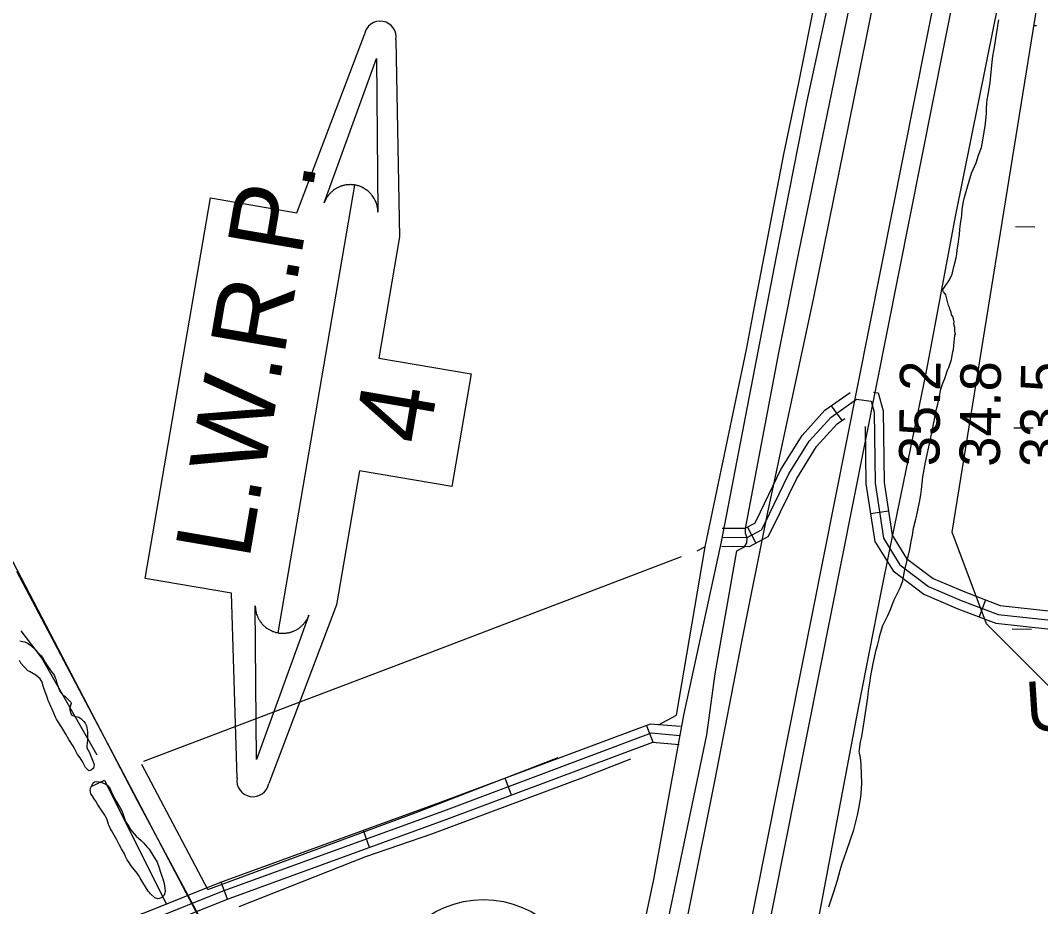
# Model space of a CAD drawing. Extents: x 3271442 to 3309282, y 752266 to 777610.
# Drawn here: x 3282681 to 3284369, y 758921 to 760386 of the extents above; entities that cross this region are included whole.
import ezdxf

# ---------------------------------------------------------------- set-up
doc = ezdxf.new("R2010")
doc.units = 0
for name, color, linetype in [('V-LEVE-TOET', 7, 'Continuous'), ('V-RAIL-TRAK', 7, 'Continuous'), ('V-RIVR-RANG', 7, 'Continuous'), ('V-RIVR-RANG-IDEN', 7, 'Continuous'), ('V-ROAD-CNTR', 7, 'Continuous'), ('V-ROAD-IDEN', 7, 'Continuous'), ('V-SITE-VEGE', 7, 'Continuous'), ('V-SURV-LINE', 7, 'Continuous'), ('V-TOPO-SHOR', 7, 'Continuous'), ('V-TOPO-WATR-IDEN', 7, 'Continuous'), ('V-WETL-SWMP', 7, 'Continuous')]:
    doc.layers.add(name, color=color, linetype=linetype)

msp = doc.modelspace()

# ---------------------------------------------------------------- linework, layer by layer
at = {"layer": 'V-LEVE-TOET'}
for points in [[(3284382.2, 761838.2), (3284344.5, 761627.4), (3284315.7, 761468.6), (3284259.5, 761217.6), (3284245.5, 761153.1), (3284211.7, 761000.5), (3284141.1, 760659.9), (3284068.8, 760300.7), (3283992.3, 759925.7), (3283917, 759573.3), (3283873.8, 759359.2), (3283829.2, 759128.8), (3283789.2, 758928.4), (3283748.2, 758723.2), (3283716.1, 758548.7), (3283700.8, 758474.2), (3283696.3, 758451.7), (3283694.3, 758422.9), (3283700.6, 758324), (3283715.2, 758155.8), (3283736.7, 757909.8), (3283747.6, 757720.6), (3283753.7, 757644)], [(3283974.8, 757644.1), (3283959.8, 757827.3), (3283934.6, 758131.3), (3283909.7, 758337.4), (3283903.2, 758406.3), (3283904.4, 758428.5), (3283911.5, 758459.3), (3283917.8, 758511.7), (3283957.3, 758687.2), (3284002, 758902.8), (3284068.3, 759252.9), (3284104.5, 759438), (3284120.1, 759514.3), (3284179.5, 759803.5), (3284227.8, 760062.5), (3284292, 760379.3), (3284364.4, 760732.6), (3284401.6, 760905.6)]]:
    msp.add_lwpolyline(points, dxfattribs=at)
at = {"layer": 'V-RAIL-TRAK'}
msp.add_lwpolyline([(3283548.1, 757644), (3283531.8, 757704.4), (3283489.6, 757836.6), (3283430.4, 757998.5), (3283369.2, 758143.7), (3283305.6, 758276.6), (3283244.5, 758396.3), (3283128.2, 758616.7), (3282975.9, 758905.4), (3282961, 758933.9), (3282846.4, 759151.6), (3282675.5, 759475.3)], dxfattribs=at)
at = {"layer": 'V-ROAD-CNTR'}
for p, q in [((3284022.6, 759749.3), (3284039.8, 759724.8)), ((3284117.2, 759575.2), (3284087.6, 759570.6)), ((3283883.9, 759548.9), (3283897.8, 759522.3)), ((3284277.6, 759428.4), (3284266.9, 759400.3)), ((3283727.7, 759193), (3283717.1, 759221.1)), ((3283493.5, 759105.4), (3283483, 759133.5)), ((3283258.8, 759018.9), (3283248.6, 759047.1)), ((3283023.9, 758933.5), (3283013.6, 758961.7))]:
    msp.add_line(p, q, dxfattribs=at)
for points in [[(3284392.4, 762318.9), (3284315.3, 761934.3), (3284255.9, 761629.7), (3284216.4, 761423.6), (3284162.8, 761165.1), (3284106.1, 760889.3), (3284031, 760479.6), (3283981.6, 760250.5), (3283931.6, 759996.1), (3283883.2, 759747.5), (3283840.4, 759524.6), (3283778.2, 759237.6), (3283728.5, 758966.2), (3283675.1, 758714.9), (3283635.4, 758490.5)], [(3281661.2, 761410.7), (3281877.3, 760997.6), (3282056.3, 760659.9), (3282250.8, 760283.5), (3282415.3, 759970.5), (3282620.5, 759583.3), (3282874.5, 759096.9), (3283005, 758852.9), (3283121.9, 758631.6), (3283211.6, 758466.4), (3283271.5, 758351.6), (3283316, 758260.4), (3283364.8, 758166.5), (3283397.9, 758090), (3283446.7, 757970.9), (3283502, 757821.2), (3283536.5, 757705.1), (3283551.4, 757646.8)], [(3283842, 759547.2), (3283879.9, 759546.8), (3283896.1, 759555.3), (3283898.7, 759560.3), (3283939.3, 759643.9), (3283974.2, 759700), (3284012.1, 759742), (3284053.6, 759771.1)], [(3284092.6, 759771.6), (3284100, 759770.6), (3284108.4, 759741.1), (3284109.9, 759622.7), (3284123.3, 759535.6), (3284147.2, 759496.8), (3284191, 759463.9), (3284243.2, 759441.5), (3284301.8, 759419.1), (3284386.7, 759409.8), (3284510.2, 759410.6), (3284567.2, 759379.4), (3284575.9, 759344.6)], [(3283841.8, 759532.2), (3283883.5, 759531.7), (3283907.2, 759544.2), (3283912.1, 759553.6), (3283952.5, 759636.6), (3283986.2, 759691), (3284022.1, 759730.7), (3284064.1, 759760.2), (3284088.3, 759757), (3284093.5, 759738.9), (3284094.9, 759621.4), (3284109, 759530.3), (3284135.9, 759486.6), (3284183.4, 759450.8), (3284237.6, 759427.6), (3284298.3, 759404.4), (3284385.9, 759394.8), (3284506.4, 759395.5), (3284554.2, 759369.4), (3284561.3, 759340.9)], [(3283841.7, 759517.2), (3283887.1, 759516.7), (3283918.4, 759533.1), (3283925.5, 759546.9), (3283965.6, 759629.4), (3283998.2, 759681.9), (3284032.1, 759719.3), (3284045.1, 759728.5)], [(3284078.7, 759715.3), (3284079.9, 759620.2), (3284094.6, 759525.1), (3284124.6, 759476.3), (3284175.8, 759437.8), (3284232, 759413.7), (3284294.7, 759389.7), (3284385.1, 759379.8), (3284502.6, 759380.5), (3284541.3, 759359.4), (3284546.7, 759337.3)], [(3283773.4, 759218.9), (3283722.7, 759223.2), (3283375.8, 759093.3), (3283010.9, 758960.7), (3282890.1, 758912.1), (3282473.8, 758758.6), (3282222.7, 758663.5), (3282085.2, 758594.3), (3281867.3, 758517), (3281707, 758457), (3281582.4, 758417.7)], [(3283772.1, 759203.9), (3283724.8, 759208), (3283380.9, 759079.2), (3283016.2, 758946.7), (3282895.5, 758898.1), (3282479.1, 758744.6), (3282228.7, 758649.7), (3282091.1, 758580.4), (3281872.4, 758502.9), (3281711.8, 758442.8), (3281586.5, 758403.2)], [(3283770.8, 759189), (3283726.9, 759192.7), (3283386.1, 759065.1), (3283021.6, 758932.7), (3282900.9, 758884.1), (3282484.3, 758730.5), (3282234.8, 758636), (3282097, 758566.6), (3281877.6, 758488.8), (3281716.7, 758428.7), (3281590.6, 758388.8)]]:
    msp.add_lwpolyline(points, dxfattribs=at)
at = {"layer": 'V-ROAD-IDEN'}
msp.add_circle((3283447.3, 758768), 165, dxfattribs=at)
at = {"layer": 'V-SITE-VEGE'}
for p, q in [((3284296.2, 760366.8), (3284297.5, 760373.1)), ((3284297.5, 760373.1), (3284298.3, 760381.9)), ((3284298.3, 760381.9), (3284299.6, 760387.7)), ((3284293.6, 760348.8), (3284294.5, 760356.3)), ((3284294.5, 760356.3), (3284296.2, 760366.8)), ((3284291.1, 760336.2), (3284293.6, 760348.8)), ((3284288.6, 760317.3), (3284289.8, 760327.4)), ((3284289.8, 760327.4), (3284291.1, 760336.2)), ((3284285.1, 760283.4), (3284287.3, 760306.8)), ((3284287.3, 760306.8), (3284288.6, 760317.3)), ((3284281.8, 760264.1), (3284285.1, 760283.4)), ((3284279.6, 760249.4), (3284280.1, 760255.3)), ((3284280.1, 760255.3), (3284281.8, 760264.1)), ((3284279.2, 760240.2), (3284279.6, 760249.4)), ((3284279.2, 760233.1), (3284279.2, 760240.2)), ((3284277.1, 760211.7), (3284277.9, 760221.3)), ((3284277.9, 760221.3), (3284279.2, 760233.1)), ((3284274.1, 760195.8), (3284277.1, 760211.7)), ((3284270.7, 760176.5), (3284273.2, 760188.7)), ((3284273.2, 760188.7), (3284274.1, 760195.8)), ((3284266.1, 760163.9), (3284270.7, 760176.5)), ((3284261.9, 760150.9), (3284266.1, 760163.9)), ((3284254.7, 760134.2), (3284261.9, 760150.9)), ((3284248, 760111.6), (3284254.7, 760134.2)), ((3284242.9, 760094), (3284245.4, 760103.6)), ((3284245.4, 760103.6), (3284248, 760111.6)), ((3284239.1, 760074.3), (3284241.2, 760087.3)), ((3284241.2, 760087.3), (3284242.9, 760094)), ((3284238.2, 760064.2), (3284239.1, 760074.3)), ((3284236.5, 760050.4), (3284238.2, 760064.2)), ((3284234.4, 760031.9), (3284235.3, 760041.6)), ((3284235.3, 760041.6), (3284236.5, 760050.4)), ((3284230.6, 760006.4), (3284233.1, 760020.6)), ((3284233.1, 760020.6), (3284234, 760029.4)), ((3284234, 760029.4), (3284234.4, 760031.9)), ((3284230.1, 760000.5), (3284230.6, 760006.4)), ((3284225.9, 759981.2), (3284228.9, 759994.2)), ((3284228.9, 759994.2), (3284230.1, 760000.5)), ((3284222.5, 759967), (3284225.9, 759981.2)), ((3284209.9, 759945.6), (3284217.9, 759957.8)), ((3284217.9, 759957.8), (3284222.5, 759967)), ((3284207, 759939.8), (3284207.8, 759941.9)), ((3284208.2, 759937.7), (3284207, 759939.8)), ((3284207.8, 759941.9), (3284209.9, 759945.6)), ((3284210.7, 759934.7), (3284208.2, 759937.7)), ((3284212, 759932.6), (3284210.7, 759934.7)), ((3284214.1, 759924.2), (3284212, 759932.6)), ((3284216.6, 759915.4), (3284214.1, 759924.2)), ((3284217.8, 759912.1), (3284216.6, 759915.4)), ((3284218.7, 759909.1), (3284217.8, 759912.1)), ((3284219.5, 759907), (3284218.7, 759909.1)), ((3284220.8, 759903.3), (3284219.5, 759907)), ((3284221.6, 759899.9), (3284220.8, 759903.3)), ((3284223.3, 759897), (3284221.6, 759899.9)), ((3284224.9, 759893.2), (3284223.3, 759897)), ((3284225.8, 759888.2), (3284224.9, 759893.2)), ((3284225.3, 759885.7), (3284225.8, 759888.2)), ((3284225.7, 759881.9), (3284225.3, 759885.7)), ((3284224.8, 759842.5), (3284227, 759865.9)), ((3284226.6, 759878.5), (3284225.7, 759881.9)), ((3284227, 759872.7), (3284226.6, 759878.5)), ((3284227.8, 759868), (3284227, 759872.7)), ((3284227, 759865.9), (3284227.8, 759868)), ((3284221.3, 759825.6), (3284223.6, 759838.6)), ((3284223.6, 759838.6), (3284224.8, 759842.5)), ((3284216.9, 759812.6), (3284221.3, 759825.6)), ((3284210.4, 759794.7), (3284215, 759808.2)), ((3284215, 759808.2), (3284216.9, 759812.6)), ((3284203.5, 759776.7), (3284207.2, 759786.7)), ((3284207.2, 759786.7), (3284210.4, 759794.7)), ((3284198.6, 759751.8), (3284203.5, 759776.7)), ((3284194.8, 759737.7), (3284198.6, 759751.8)), ((3284193.1, 759726.7), (3284194.8, 759737.7)), ((3284189.3, 759708.4), (3284193.1, 759726.7)), ((3284186.4, 759694.2), (3284189.3, 759708.4)), ((3284178.3, 759656.4), (3284186.4, 759694.2)), ((3284173.7, 759632.1), (3284177, 759650.2)), ((3284177, 759650.2), (3284178.3, 759656.4)), ((3284172.9, 759621.4), (3284173.7, 759632.1)), ((3284171.8, 759610.8), (3284172.9, 759621.4)), ((3284168.5, 759589.8), (3284170.5, 759601.9)), ((3284170.5, 759601.9), (3284171.8, 759610.8)), ((3284163.4, 759566.1), (3284168.5, 759589.8)), ((3284162.1, 759562), (3284163.4, 759566.1)), ((3284156.6, 759535.7), (3284158.6, 759547.2)), ((3284158.6, 759547.2), (3284162.1, 759562)), ((3284154.6, 759525), (3284156.6, 759535.7)), ((3284151.7, 759509.1), (3284154.6, 759525)), ((3284144.3, 759478.6), (3284151.7, 759509.1)), ((3284142, 759466.8), (3284144.3, 759478.6)), ((3284140.7, 759459.7), (3284142, 759466.8)), ((3284126.8, 759428.8), (3284136.7, 759448.2)), ((3284136.7, 759448.2), (3284140.7, 759459.7)), ((3284122.8, 759418.5), (3284126.8, 759428.8)), ((3284116, 759402.6), (3284120.3, 759412.6)), ((3284120.3, 759412.6), (3284122.8, 759418.5)), ((3284108, 759386.1), (3284112.6, 759396.1)), ((3284112.6, 759396.1), (3284116, 759402.6)), ((3284102.3, 759367.8), (3284108, 759386.1)), ((3284099.1, 759353), (3284101.7, 759364)), ((3284101.7, 759364), (3284102.3, 759367.8)), ((3284091.8, 759323.2), (3284096.9, 759345.9)), ((3284096.9, 759345.9), (3284099.1, 759353)), ((3284087.5, 759300.1), (3284091.8, 759323.2)), ((3284084.2, 759278.2), (3284086.8, 759294.8)), ((3284086.8, 759294.8), (3284087.5, 759300.1)), ((3284082.8, 759267), (3284084.2, 759278.2)), ((3284080.1, 759248.9), (3284082.8, 759267)), ((3284077.4, 759230.6), (3284080.1, 759248.9)), ((3284073, 759202.7), (3284077.4, 759230.6)), ((3284070.2, 759189.7), (3284070.8, 759193.9)), ((3284070.8, 759193.9), (3284073, 759202.7)), ((3284068.8, 759178.2), (3284069.4, 759180.6)), ((3284069, 759175.2), (3284068.8, 759178.2)), ((3284070.7, 759167.8), (3284069, 759175.2)), ((3284069.4, 759180.6), (3284070.2, 759189.7)), ((3284071.9, 759156.2), (3284070.7, 759167.8)), ((3284073.2, 759125), (3284071.9, 759156.2)), ((3284072, 759108.4), (3284073.2, 759125)), ((3284071.3, 759102.2), (3284072, 759108.4)), ((3284068.3, 759083.8), (3284071.3, 759102.2)), ((3284065.7, 759072.3), (3284068.3, 759083.8)), ((3284060, 759048.1), (3284065.7, 759072.3)), ((3284048.4, 759014.5), (3284060, 759048.1)), ((3284043.1, 759000.3), (3284048.4, 759014.5)), ((3284037.1, 758981.7), (3284040, 758991.2)), ((3284040, 758991.2), (3284043.1, 759000.3)), ((3284032.7, 758964.9), (3284037.1, 758981.7)), ((3284026.7, 758946), (3284032.7, 758964.9)), ((3284022.7, 758934.2), (3284025.5, 758942.2)), ((3284025.5, 758942.2), (3284026.7, 758946)), ((3284018.6, 758921.2), (3284022.7, 758934.2))]:
    msp.add_line(p, q, dxfattribs=at)
msp.add_lwpolyline([(3282680.5, 759360.9), (3282684.9, 759359.6), (3282688.8, 759359), (3282690.9, 759358.1), (3282694.4, 759356.5), (3282698.2, 759353.8), (3282706.9, 759345.3), (3282709, 759342.6), (3282713.1, 759338.7), (3282714.8, 759336.9), (3282717.7, 759333.2), (3282720.9, 759328.1), (3282722.9, 759324.5), (3282725.8, 759319.8), (3282733.6, 759308.9), (3282736.2, 759305.6), (3282737.7, 759302.9), (3282739.1, 759299.6), (3282739.9, 759297.3), (3282741.6, 759290.7), (3282745.8, 759278.5), (3282748.2, 759275.2), (3282750.2, 759272.7), (3282752.2, 759270.9), (3282754.6, 759269.1), (3282761.3, 759262.8), (3282763.3, 759260.9), (3282764.8, 759259.4), (3282765.1, 759257.4), (3282764.4, 759253.8), (3282762.8, 759248.5), (3282763.4, 759245.2), (3282765, 759239.8), (3282766.5, 759238), (3282769.1, 759236.8), (3282778, 759234.3), (3282781.5, 759232.4), (3282786.5, 759227.6), (3282788.5, 759224.6), (3282790.5, 759220.4), (3282792.1, 759210.3), (3282792.5, 759198.4), (3282791.8, 759190.7), (3282791.1, 759188.1), (3282791.4, 759184.5), (3282793.4, 759179.4), (3282795.1, 759177), (3282796, 759174.6), (3282797.4, 759171.9), (3282800.5, 759163.3), (3282802.8, 759157.9), (3282803.3, 759155.2), (3282803, 759152.8), (3282802.4, 759150.2), (3282798.4, 759146.7), (3282794.3, 759145.9), (3282789, 759151.3), (3282786.7, 759155.5), (3282784.4, 759160.3), (3282780.1, 759167.2), (3282776, 759172.9), (3282771.2, 759181.9), (3282768.6, 759186.4), (3282761.6, 759197.5), (3282756.4, 759206.2), (3282749.8, 759217.6), (3282747.5, 759220.6), (3282741.2, 759231.4), (3282739.4, 759234.7), (3282734, 759247.8), (3282731.7, 759252), (3282728.9, 759258.6), (3282727.2, 759262.2), (3282724.9, 759269.3), (3282720.7, 759281), (3282718.7, 759287.5), (3282717.9, 759291.1), (3282715.6, 759295.3), (3282713.8, 759297.7), (3282706.8, 759304.1), (3282696.5, 759310.2), (3282693.9, 759311.4), (3282687.5, 759317.5), (3282681.9, 759323.8), (3282679.7, 759328.3)], dxfattribs=at)
msp.add_lwpolyline([(3282803.5, 759099.7), (3282799.8, 759105.1), (3282797.8, 759107.8), (3282797, 759114.1), (3282797.9, 759118.2), (3282801.6, 759126.2), (3282804, 759127.9), (3282807.9, 759128.4), (3282810.9, 759127.8), (3282815.9, 759126.5), (3282822.7, 759123.7), (3282825.6, 759121.6), (3282829.4, 759117.1), (3282830.8, 759113.5), (3282832.2, 759110.8), (3282833.6, 759106.6), (3282840, 759095.8), (3282848.9, 759079.6), (3282850.9, 759075.5), (3282852.3, 759070.4), (3282854, 759065.3), (3282855.4, 759062), (3282861.2, 759053.3), (3282864.1, 759048.2), (3282866.1, 759045.5), (3282872.8, 759038), (3282881.3, 759030.7), (3282885.4, 759026.5), (3282887.7, 759023.5), (3282891.8, 759019.3), (3282894.1, 759016.5), (3282896.1, 759013.8), (3282907.6, 758994.7), (3282911.1, 758985.7), (3282912.4, 758979.7), (3282915.3, 758971.4), (3282916.7, 758967.5), (3282919.2, 758959.4), (3282920.5, 758951.7), (3282921, 758946.1), (3282920.1, 758944), (3282918.9, 758940.5), (3282915.2, 758936.4), (3282911.4, 758934.9), (3282908.7, 758934.4), (3282903.7, 758935.7), (3282896.6, 758942.3), (3282894.9, 758944.4), (3282892.9, 758947.1), (3282879.6, 758968.1), (3282877.9, 758971.4), (3282874.4, 758976.8), (3282864.5, 758988.9), (3282860.5, 758994.6), (3282858.2, 758998.5), (3282855, 759004.2), (3282853.3, 759008.4), (3282848.4, 759016.7), (3282845.2, 759022.7), (3282842.4, 759028.7), (3282840.6, 759032), (3282834, 759043.4), (3282832, 759047.3), (3282830.6, 759049.7), (3282828, 759054.8), (3282827.1, 759057.2), (3282825.2, 759063.4), (3282824.3, 759066.4), (3282822.3, 759070.3), (3282820.9, 759072.7), (3282817.7, 759077.5), (3282809.6, 759089.5), (3282806.1, 759095.5)], close=True, dxfattribs=at)
at = {"layer": 'V-SURV-LINE'}
for points in [[(3283803.5, 758460.8), (3284273.7, 760825.4)], [(3284303.1, 760819.6), (3283832.9, 758454.9)]]:
    msp.add_lwpolyline(points, dxfattribs=at)
at = {"layer": 'V-TOPO-SHOR'}
msp.add_line((3282991.3, 758949.7), (3282882.1, 759156.2), dxfattribs=at)
for points in [[(3283742, 758848.8), (3283816.9, 759205.2), (3283830.2, 759306.1), (3283866.4, 759509.3), (3283873.4, 759513.4), (3283878.9, 759516.1), (3283883.1, 759523), (3283883.2, 759531.3), (3283880.5, 759538.2), (3283880.6, 759546.5), (3283935.6, 759836.7), (3283968.8, 760002.5), (3284052.3, 760406), (3284068.2, 760479.2), (3284118.8, 760747.3), (3284154.9, 760926.9), (3284202.6, 761177)], [(3283814, 759516), (3283882.5, 759842.4), (3283895.8, 759912.7), (3283944.1, 760165.4), (3283968.2, 760280.7), (3284024.8, 760563.3), (3284039.1, 760623.3), (3284038, 760623.3), (3284057.4, 760731.7)], [(3283736.5, 759222), (3283766.6, 759237.9), (3283814, 759516), (3283800.1, 759509.1)], [(3282885.6, 759162), (3283338.8, 759333.9), (3283774.6, 759500.1)], [(3282808.3, 759171.9), (3282716, 759333.2), (3282682.9, 759377.4)], [(3282991.3, 758949.7), (3283334.3, 759076.2), (3283570.8, 759167.9)], [(3283043.1, 758921.5), (3283252.9, 759004.1), (3283361.8, 759041.4), (3283613.3, 759135.2), (3283690.9, 759165.7)], [(3282798.6, 759119.9), (3282820.6, 759130.2), (3282922.9, 758924.8)]]:
    msp.add_lwpolyline(points, dxfattribs=at)
at = {"layer": 'V-TOPO-WATR-IDEN'}
msp.add_line((3283107.8, 759373.9), (3283234.6, 760114.3), dxfattribs=at)
for points in [[(3283039.8, 759133.9), (3283030.5, 759439.3), (3282887.8, 759463.7), (3282995.6, 760093.1), (3283138.3, 760068.6), (3283250.3, 760363.2)], [(3283302.5, 760354.2), (3283308.4, 760028.7), (3283274, 759828.2), (3283427.1, 759802), (3283395.2, 759615.7), (3283242.1, 759641.9), (3283204.2, 759420.3), (3283092, 759125)]]:
    msp.add_lwpolyline(points, dxfattribs=at)
for points in [[(3283183.9, 760084.9), (3283270.4, 760323.7), (3283272.6, 760069.7), (3283272.3, 760074.3), (3283271.6, 760078.7), (3283271.2, 760080.4), (3283270.8, 760081.9), (3283270.2, 760083.7), (3283269.6, 760085.4), (3283269, 760086.9), (3283268.1, 760088.9), (3283267.1, 760091), (3283266.4, 760092.1), (3283265.6, 760093.5), (3283264.4, 760095.4), (3283263.3, 760096.8), (3283262.2, 760098.2), (3283261.4, 760099.2), (3283260.5, 760100.2), (3283259.4, 760101.3), (3283258.3, 760102.4), (3283257.2, 760103.4), (3283256.3, 760104.2), (3283254.9, 760105.4), (3283253.4, 760106.4), (3283252.3, 760107.2), (3283250.9, 760108.1), (3283249.7, 760108.8), (3283248.6, 760109.5), (3283247.7, 760109.9), (3283246.3, 760110.6), (3283244.9, 760111.2), (3283243.6, 760111.8), (3283242.2, 760112.3), (3283240.9, 760112.8), (3283239.4, 760113.2), (3283238.2, 760113.5), (3283236.5, 760113.9), (3283234.6, 760114.3), (3283233.9, 760114.4), (3283233, 760114.5), (3283231.9, 760114.7), (3283230.9, 760114.8), (3283229.8, 760114.9), (3283228.8, 760114.9), (3283227.6, 760115), (3283226.8, 760115), (3283225.6, 760114.9), (3283224.5, 760114.9), (3283223.7, 760114.9), (3283221.7, 760114.7), (3283220.6, 760114.5), (3283219.9, 760114.4), (3283218.6, 760114.2), (3283217.6, 760114), (3283216.5, 760113.8), (3283215.2, 760113.4), (3283213.9, 760113.1), (3283213, 760112.8), (3283212.2, 760112.6), (3283211.1, 760112.2), (3283210.2, 760111.8), (3283209.1, 760111.4), (3283207.9, 760110.9), (3283206.8, 760110.4), (3283205.5, 760109.7), (3283204.5, 760109.1), (3283203.4, 760108.5), (3283202.4, 760107.9), (3283201.6, 760107.4), (3283200.7, 760106.8), (3283199.4, 760105.8), (3283199.4, 760105.8), (3283198.6, 760105.2), (3283198.1, 760104.8), (3283197.3, 760104.2), (3283196.3, 760103.3), (3283195.6, 760102.6), (3283194.9, 760102), (3283194.1, 760101.1), (3283193.3, 760100.3), (3283192.7, 760099.7), (3283192, 760098.9), (3283191.1, 760097.8), (3283190.6, 760097.1), (3283190.2, 760096.6), (3283189.8, 760096.1), (3283189.4, 760095.5), (3283188.8, 760094.7), (3283188.3, 760093.8), (3283187.8, 760093), (3283187.3, 760092.2), (3283186.7, 760091.1), (3283186.3, 760090.4), (3283185.8, 760089.4), (3283185.2, 760088.1), (3283184.8, 760087.2), (3283184.5, 760086.5), (3283184.2, 760085.8), (3283184, 760085.3)], [(3283158.4, 759403.2), (3283071.9, 759164.5), (3283069.7, 759418.4), (3283070, 759413.9), (3283070.7, 759409.5), (3283071.1, 759407.8), (3283071.5, 759406.3), (3283072.1, 759404.5), (3283072.7, 759402.8), (3283073.3, 759401.3), (3283074.2, 759399.3), (3283075.2, 759397.2), (3283075.9, 759396.1), (3283076.7, 759394.7), (3283077.9, 759392.8), (3283079, 759391.4), (3283080.1, 759390), (3283080.9, 759389), (3283081.8, 759388), (3283082.9, 759386.8), (3283084, 759385.8), (3283085.1, 759384.8), (3283086, 759384), (3283087.5, 759382.8), (3283088.9, 759381.8), (3283090, 759381), (3283091.4, 759380.1), (3283092.6, 759379.3), (3283093.7, 759378.7), (3283094.6, 759378.3), (3283096, 759377.6), (3283097.4, 759377), (3283098.7, 759376.4), (3283100.1, 759375.9), (3283101.4, 759375.4), (3283102.9, 759375), (3283104.1, 759374.7), (3283105.8, 759374.3), (3283107.8, 759373.9), (3283108.4, 759373.8), (3283109.3, 759373.6), (3283110.4, 759373.5), (3283111.4, 759373.4), (3283112.5, 759373.3), (3283113.5, 759373.3), (3283114.7, 759373.2), (3283115.5, 759373.2), (3283116.7, 759373.2), (3283117.9, 759373.3), (3283118.6, 759373.3), (3283120.6, 759373.5), (3283121.7, 759373.7), (3283122.5, 759373.8), (3283123.7, 759374), (3283124.7, 759374.2), (3283125.8, 759374.4), (3283127.2, 759374.7), (3283128.4, 759375.1), (3283129.3, 759375.4), (3283130.1, 759375.6), (3283131.2, 759376), (3283132.1, 759376.4), (3283133.3, 759376.8), (3283134.4, 759377.3), (3283135.5, 759377.8), (3283136.9, 759378.5), (3283137.8, 759379.1), (3283138.9, 759379.7), (3283139.9, 759380.3), (3283140.7, 759380.8), (3283141.6, 759381.4), (3283142.9, 759382.3), (3283142.9, 759382.4), (3283143.7, 759382.9), (3283144.2, 759383.4), (3283145, 759384), (3283146, 759384.9), (3283146.7, 759385.6), (3283147.4, 759386.2), (3283148.2, 759387), (3283149, 759387.9), (3283149.6, 759388.5), (3283150.3, 759389.3), (3283151.2, 759390.4), (3283151.7, 759391.1), (3283152.1, 759391.6), (3283152.5, 759392.1), (3283152.9, 759392.7), (3283153.5, 759393.5), (3283154, 759394.4), (3283154.5, 759395.2), (3283155, 759396), (3283155.7, 759397.1), (3283156, 759397.8), (3283156.5, 759398.8), (3283157.1, 759400.1), (3283157.6, 759401), (3283157.9, 759401.7), (3283158.1, 759402.4), (3283158.3, 759402.9)]]:
    msp.add_lwpolyline(points, close=True, dxfattribs=at)
for centre, start, end in [((3283276.4, 760358.7), 350.2818, 170.2818), ((3283065.9, 759129.5), 170.2818, 350.2818)]:
    msp.add_arc(centre, 26.5, start, end, dxfattribs=at)
at = {"layer": 'V-WETL-SWMP'}
for p, q in [((3284222.4, 759540.2), (3284468.5, 761065.5)), ((3284357.6, 760378.1), (3284361.8, 760378.1)), ((3284327.1, 760045.7), (3284359.1, 760045.4)), ((3284324.3, 759713), (3284356.3, 759712.8)), ((3284279.2, 759388.6), (3284222.4, 759540.2)), ((3284421.2, 759246.5), (3284279.2, 759388.6)), ((3284321.6, 759380.4), (3284353.6, 759380.1))]:
    msp.add_line(p, q, dxfattribs=at)

# ---------------------------------------------------------------- texts
at = {"layer": 'V-RIVR-RANG'}
for s, p in [('35.2', (3284201.3, 759649.2)), ('34.8', (3284301.3, 759648.3)), ('33.5', (3284401.3, 759647.4))]:
    msp.add_text(s, height=67, rotation=89.3383, dxfattribs=at).set_placement(p)
at = {"layer": 'V-RIVR-RANG-IDEN'}
msp.add_text('U-10', height=83, rotation=3.8183, dxfattribs=at).set_placement((3284346.8, 759209.7))
at = {"layer": 'V-TOPO-WATR-IDEN'}
for s, rotation, p in [('L.W.R.P.', 80.2817, (3283059.6, 759492.9)), ('4', 80.2818, (3283355.4, 759682.5))]:
    msp.add_text(s, height=124.5, rotation=rotation, dxfattribs=at).set_placement(p)

doc.saveas('drawing.dxf')
